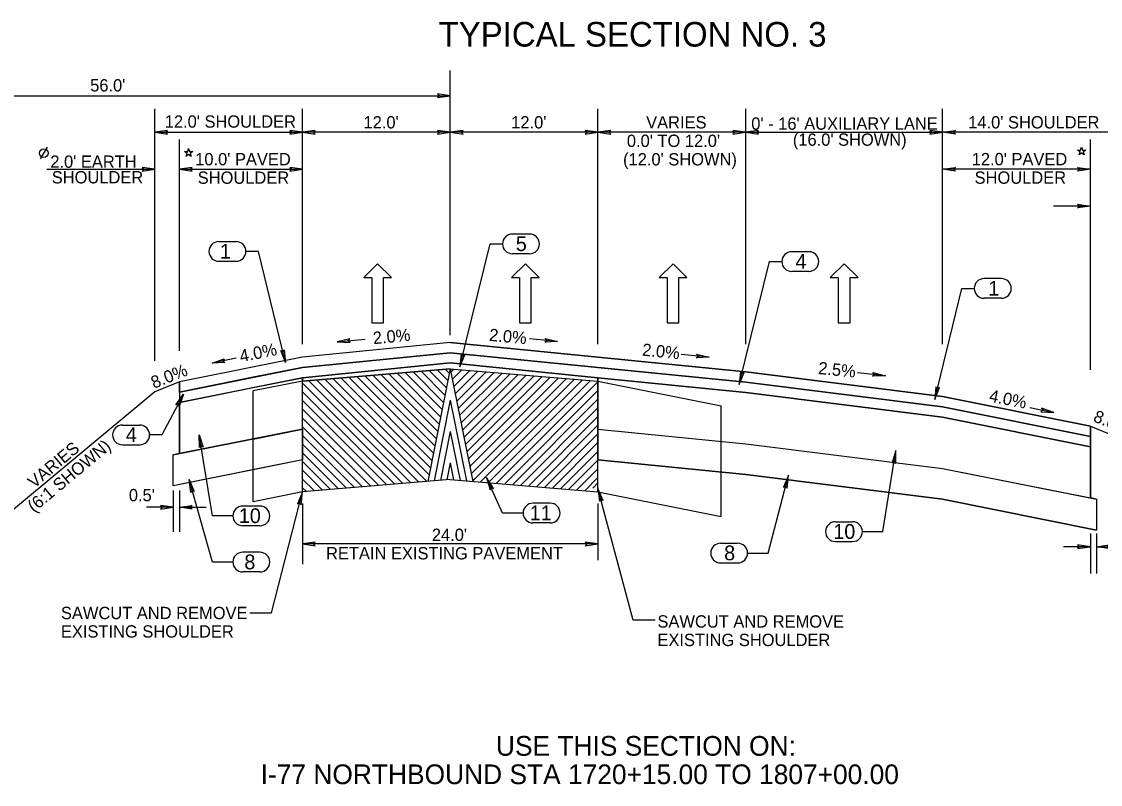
# Model space of a CAD drawing. Extents: x 2003207 to 2014043, y 843846 to 860154.
# Drawn here: x 2013648 to 2013735.7, y 844713 to 844774.9 of the extents above; entities that cross this region are included whole.
import ezdxf

# ---------------------------------------------------------------- set-up
doc = ezdxf.new("R2010")
doc.units = 0
for name, color, linetype in [('RD_EX_Road', 7, 'Continuous'), ('RD_EX_Road_txCode', 7, 'Continuous'), ('RD_QTY_Base_Course', 7, 'Continuous'), ('RD_QTY_ConcPave', 7, 'Continuous'), ('RD_QTY_Intermediate', 7, 'Continuous'), ('RD_QTY_PermVeg', 7, 'Continuous'), ('RD_QTY_Surf_Course', 7, 'Continuous'), ('RD_TX_Misc2', 7, 'Continuous'), ('RD_TX_TypSect', 7, 'Continuous')]:
    doc.layers.add(name, color=color, linetype=linetype)

msp = doc.modelspace()

# ---------------------------------------------------------------- linework, layer by layer
at = {"layer": 'RD_EX_Road'}
for p, q in [((2013682.86, 844747.226), (2013679.704, 844746.91)), ((2013682.86, 844746.75), (2013670.86, 844745.75)), ((2013676.576, 844746.226), (2013681.725, 844741.078)), ((2013677.229, 844746.281), (2013681.843, 844741.667)), ((2013677.882, 844746.335), (2013681.961, 844742.256)), ((2013678.534, 844746.39), (2013682.079, 844742.845)), ((2013679.187, 844746.444), (2013682.197, 844743.435)), ((2013679.84, 844746.498), (2013682.315, 844744.024)), ((2013680.493, 844746.553), (2013682.432, 844744.613)), ((2013682.86, 844746.75), (2013681.03, 844737.602)), ((2013681.145, 844746.607), (2013682.55, 844745.202)), ((2013681.798, 844746.662), (2013682.668, 844745.792)), ((2013682.451, 844746.716), (2013682.786, 844746.381)), ((2013682.86, 844746.75), (2013684.689, 844737.602)), ((2013682.86, 844746.75), (2013694.86, 844745.75)), ((2013682.913, 844746.483), (2013683.156, 844746.725)), ((2013683.031, 844745.894), (2013683.809, 844746.671)), ((2013683.149, 844745.304), (2013684.461, 844746.617)), ((2013683.267, 844744.715), (2013685.114, 844746.562)), ((2013683.385, 844744.126), (2013685.767, 844746.508)), ((2013683.503, 844743.537), (2013686.419, 844746.453)), ((2013683.62, 844742.947), (2013687.072, 844746.399)), ((2013683.738, 844742.358), (2013687.725, 844746.345)), ((2013683.856, 844741.769), (2013688.378, 844746.29)), ((2013683.974, 844741.179), (2013689.03, 844746.236)), ((2013670.86, 844745.75), (2013666.86, 844744.95)), ((2013670.86, 844736.754), (2013670.86, 844745.75)), ((2013670.86, 844745.579), (2013679.006, 844737.433)), ((2013671.355, 844745.791), (2013679.658, 844737.487)), ((2013672.007, 844745.846), (2013680.311, 844737.542)), ((2013672.66, 844745.9), (2013680.964, 844737.596)), ((2013673.313, 844745.955), (2013681.136, 844738.131)), ((2013673.965, 844746.009), (2013681.254, 844738.721)), ((2013674.618, 844746.063), (2013681.372, 844739.31)), ((2013675.271, 844746.118), (2013681.49, 844739.899)), ((2013675.924, 844746.172), (2013681.607, 844740.488)), ((2013684.092, 844740.59), (2013689.683, 844746.182)), ((2013684.21, 844740.001), (2013690.336, 844746.127)), ((2013684.327, 844739.412), (2013690.988, 844746.073)), ((2013684.445, 844738.822), (2013691.641, 844746.018)), ((2013684.563, 844738.233), (2013692.294, 844745.964)), ((2013684.681, 844737.644), (2013692.947, 844745.91)), ((2013685.295, 844737.551), (2013693.599, 844745.855)), ((2013685.935, 844737.483), (2013694.252, 844745.801)), ((2013686.601, 844737.442), (2013694.905, 844745.746)), ((2013694.86, 844745.75), (2013704.86, 844743.75)), ((2013694.86, 844736.754), (2013694.86, 844745.75)), ((2013666.86, 844735.954), (2013666.86, 844744.95)), ((2013670.86, 844744.872), (2013678.353, 844737.379)), ((2013687.254, 844737.388), (2013694.86, 844744.994)), ((2013670.86, 844744.165), (2013677.7, 844737.324)), ((2013682.86, 844744.201), (2013681.549, 844737.645)), ((2013682.86, 844744.201), (2013684.171, 844737.645)), ((2013687.906, 844737.334), (2013694.86, 844744.287)), ((2013704.86, 844734.754), (2013704.86, 844743.75)), ((2013670.86, 844743.458), (2013677.048, 844737.27)), ((2013670.86, 844742.751), (2013676.395, 844737.215)), ((2013688.559, 844737.279), (2013694.86, 844743.58)), ((2013689.212, 844737.225), (2013694.86, 844742.873)), ((2013670.86, 844742.044), (2013675.742, 844737.161)), ((2013689.864, 844737.171), (2013694.86, 844742.166)), ((2013670.86, 844741.336), (2013675.089, 844737.107)), ((2013682.86, 844741.651), (2013682.067, 844737.688)), ((2013682.86, 844741.651), (2013683.652, 844737.688)), ((2013690.517, 844737.116), (2013694.86, 844741.459)), ((2013670.86, 844740.629), (2013674.437, 844737.052)), ((2013691.17, 844737.062), (2013694.86, 844740.752)), ((2013670.86, 844739.922), (2013673.784, 844736.998)), ((2013670.86, 844739.215), (2013673.131, 844736.944)), ((2013691.823, 844737.007), (2013694.86, 844740.045)), ((2013692.475, 844736.953), (2013694.86, 844739.337)), ((2013670.86, 844738.508), (2013672.479, 844736.889)), ((2013682.86, 844739.102), (2013682.586, 844737.731)), ((2013682.86, 844739.102), (2013683.134, 844737.731)), ((2013693.128, 844736.899), (2013694.86, 844738.63)), ((2013670.86, 844737.801), (2013671.826, 844736.835)), ((2013682.86, 844737.754), (2013670.86, 844736.754)), ((2013682.86, 844737.754), (2013694.86, 844736.754)), ((2013693.781, 844736.844), (2013694.86, 844737.923)), ((2013694.433, 844737.065), (2013694.86, 844737.491)), ((2013670.86, 844736.754), (2013666.86, 844735.954)), ((2013670.86, 844737.094), (2013671.173, 844736.78)), ((2013694.86, 844736.754), (2013704.86, 844734.754))]:
    msp.add_line(p, q, dxfattribs=at)
at = {"layer": 'RD_QTY_Base_Course'}
for p, q in [((2013694.86, 844741.859), (2013694.86, 844739.359)), ((2013660.36, 844739.759), (2013666.86, 844741.059)), ((2013660.86, 844739.859), (2013660.36, 844739.759)), ((2013660.36, 844737.259), (2013660.36, 844739.759)), ((2013660.36, 844737.259), (2013660.36, 844739.759)), ((2013670.86, 844739.359), (2013660.86, 844737.359)), ((2013694.86, 844739.359), (2013706.86, 844738.159)), ((2013666.86, 844738.559), (2013660.36, 844737.259)), ((2013706.86, 844738.159), (2013722.86, 844736.159)), ((2013660.36, 844737.259), (2013660.36, 844737.259)), ((2013722.86, 844736.159), (2013735.36, 844733.659)), ((2013735.36, 844736.159), (2013734.86, 844736.259)), ((2013735.36, 844736.159), (2013735.36, 844733.659))]:
    msp.add_line(p, q, dxfattribs=at)
msp.add_lwpolyline([(2013666.86, 844741.059), (2013666.86, 844741.041), (2013670.86, 844741.859), (2013670.86, 844739.359), (2013666.86, 844738.559)], dxfattribs=at)
msp.add_lwpolyline([(2013694.86, 844741.859), (2013706.86, 844740.659), (2013722.86, 844738.659), (2013735.36, 844736.159), (2013735.36, 844733.659), (2013722.86, 844736.159), (2013706.86, 844738.159), (2013694.86, 844739.359)], close=True, dxfattribs=at)
at = {"layer": 'RD_QTY_ConcPave'}
for p, q in [((2013694.86, 844747.692), (2013706.86, 844746.492)), ((2013660.86, 844745.692), (2013660.86, 844744.025)), ((2013722.86, 844744.492), (2013734.86, 844742.092)), ((2013660.86, 844739.859), (2013660.86, 844744.025)), ((2013722.86, 844742.826), (2013734.86, 844740.426)), ((2013670.86, 844741.859), (2013660.86, 844739.859)), ((2013694.86, 844741.859), (2013706.86, 844740.659)), ((2013734.86, 844742.092), (2013734.86, 844741.259)), ((2013706.86, 844740.659), (2013722.86, 844738.659)), ((2013734.86, 844740.425), (2013734.86, 844736.259)), ((2013722.86, 844738.659), (2013734.86, 844736.259))]:
    msp.add_line(p, q, dxfattribs=at)
for points in [[(2013670.86, 844746.025), (2013660.86, 844744.025), (2013660.86, 844739.859), (2013670.86, 844741.859)], [(2013694.86, 844746.026), (2013694.86, 844741.859), (2013706.86, 844740.659), (2013722.86, 844738.659), (2013734.86, 844736.259), (2013734.86, 844740.425), (2013722.86, 844742.826), (2013706.86, 844744.826)]]:
    msp.add_lwpolyline(points, close=True, dxfattribs=at)
at = {"layer": 'RD_QTY_Intermediate'}
for p, q in [((2013682.86, 844748.059), (2013670.86, 844746.859)), ((2013682.86, 844748.059), (2013694.86, 844746.859)), ((2013682.86, 844747.226), (2013670.86, 844746.026)), ((2013682.86, 844747.226), (2013694.86, 844746.026)), ((2013694.86, 844746.026), (2013682.86, 844747.226)), ((2013670.86, 844746.859), (2013660.86, 844744.859)), ((2013682.86, 844746.75), (2013670.86, 844745.75)), ((2013670.86, 844745.75), (2013682.86, 844746.75)), ((2013682.86, 844746.75), (2013694.86, 844745.75)), ((2013682.86, 844746.75), (2013694.86, 844745.75)), ((2013694.86, 844746.859), (2013706.86, 844745.659)), ((2013670.86, 844746.025), (2013660.86, 844744.025)), ((2013670.86, 844745.75), (2013670.86, 844746.025)), ((2013670.86, 844746.025), (2013670.86, 844746.025)), ((2013670.86, 844746.025), (2013670.86, 844745.75)), ((2013670.86, 844745.75), (2013670.86, 844745.75)), ((2013670.86, 844745.75), (2013670.86, 844745.75)), ((2013694.86, 844746.026), (2013706.86, 844744.826)), ((2013694.86, 844746.026), (2013694.86, 844745.75)), ((2013694.86, 844745.75), (2013694.86, 844746.026)), ((2013706.86, 844745.659), (2013722.86, 844743.659)), ((2013660.86, 844744.859), (2013660.86, 844744.025)), ((2013706.86, 844744.826), (2013722.86, 844742.826)), ((2013722.86, 844743.659), (2013734.86, 844741.259)), ((2013722.86, 844742.825), (2013734.86, 844740.425)), ((2013734.86, 844741.259), (2013734.86, 844740.425))]:
    msp.add_line(p, q, dxfattribs=at)
msp.add_lwpolyline([(2013670.86, 844746.025), (2013682.86, 844747.226), (2013706.86, 844744.826), (2013722.86, 844742.826), (2013734.86, 844740.425), (2013734.86, 844741.259), (2013722.86, 844743.659), (2013706.86, 844745.659), (2013682.86, 844748.059), (2013670.86, 844746.859), (2013666.86, 844746.059), (2013660.86, 844744.859), (2013660.86, 844744.025), (2013666.86, 844745.225)], close=True, dxfattribs=at)
msp.add_lwpolyline([(2013682.86, 844747.226), (2013679.704, 844746.91), (2013670.86, 844746.025)], dxfattribs=at)
at = {"layer": 'RD_QTY_PermVeg'}
for p, q in [((2013660.86, 844745.692), (2013658.86, 844744.892)), ((2013658.86, 844744.892), (2013626.86, 844718.225)), ((2013734.86, 844742.092), (2013736.86, 844741.292))]:
    msp.add_line(p, q, dxfattribs=at)
at = {"layer": 'RD_QTY_Surf_Course'}
for p, q in [((2013682.86, 844748.892), (2013670.86, 844747.692)), ((2013682.86, 844748.892), (2013694.86, 844747.692)), ((2013670.86, 844747.692), (2013660.86, 844745.692)), ((2013706.86, 844746.492), (2013722.86, 844744.492)), ((2013660.86, 844744.859), (2013660.86, 844745.692)), ((2013660.86, 844741.525), (2013660.86, 844740.863))]:
    msp.add_line(p, q, dxfattribs=at)
msp.add_lwpolyline([(2013694.86, 844746.859), (2013706.86, 844745.659), (2013722.86, 844743.659), (2013734.86, 844741.259), (2013734.86, 844742.092), (2013722.86, 844744.492), (2013706.86, 844746.492), (2013694.86, 844747.692), (2013682.86, 844748.892), (2013670.86, 844747.692), (2013660.86, 844745.692), (2013660.86, 844744.859), (2013670.86, 844746.859), (2013682.86, 844748.059)], close=True, dxfattribs=at)
at = {"layer": 'RD_TX_Misc2'}
for p, q in [((2013689.304, 844757.692), (2013687.904, 844757.692)), ((2013664.06, 844757.077), (2013665.46, 844757.077)), ((2013689.304, 844756.092), (2013687.904, 844756.092)), ((2013711.998, 844756.255), (2013710.598, 844756.255)), ((2013664.06, 844755.477), (2013665.46, 844755.477)), ((2013711.998, 844754.655), (2013710.598, 844754.655)), ((2013727.633, 844754.071), (2013726.233, 844754.071)), ((2013727.633, 844752.471), (2013726.233, 844752.471)), ((2013656.233, 844742.182), (2013657.633, 844742.182)), ((2013656.233, 844740.582), (2013657.633, 844740.582)), ((2013690.98, 844735.835), (2013689.58, 844735.835)), ((2013667.4, 844735.606), (2013666, 844735.606)), ((2013667.4, 844734.006), (2013666, 844734.006)), ((2013690.98, 844734.235), (2013689.58, 844734.235)), ((2013714.144, 844734.326), (2013715.544, 844734.326)), ((2013704.821, 844732.585), (2013706.221, 844732.585)), ((2013714.144, 844732.726), (2013715.544, 844732.726)), ((2013667.4, 844731.852), (2013666, 844731.852)), ((2013704.821, 844730.985), (2013706.221, 844730.985)), ((2013667.4, 844730.252), (2013666, 844730.252))]:
    msp.add_line(p, q, dxfattribs=at)
for centre, start, end in [((2013687.904, 844756.892), 90, 270), ((2013689.304, 844756.892), 270, 90), ((2013664.06, 844756.277), 90, 270), ((2013665.46, 844756.277), 270, 90), ((2013710.598, 844755.455), 90, 270), ((2013711.998, 844755.455), 270, 90), ((2013726.233, 844753.271), 90, 270), ((2013727.633, 844753.271), 270, 90), ((2013656.233, 844741.382), 90, 270), ((2013657.633, 844741.382), 270, 90), ((2013689.58, 844735.035), 90, 270), ((2013690.98, 844735.035), 270, 90), ((2013666, 844734.806), 90, 270), ((2013667.4, 844734.806), 270, 90), ((2013714.144, 844733.526), 90, 270), ((2013715.544, 844733.526), 270, 90), ((2013704.821, 844731.785), 90, 270), ((2013706.221, 844731.785), 270, 90), ((2013666, 844731.052), 90, 270), ((2013667.4, 844731.052), 270, 90)]:
    msp.add_arc(centre, 0.8, start, end, dxfattribs=at)
at = {"layer": 'RD_TX_TypSect'}
for p, q in [((2013682.86, 844749.482), (2013682.86, 844770.976)), ((2013626.86, 844768.924), (2013682.86, 844768.924)), ((2013658.86, 844747.384), (2013658.86, 844767.863)), ((2013670.86, 844748.751), (2013670.86, 844767.863)), ((2013694.86, 844748.751), (2013694.86, 844767.863)), ((2013706.86, 844748.751), (2013706.86, 844767.863)), ((2013722.86, 844748.751), (2013722.86, 844767.863)), ((2013658.86, 844765.956), (2013670.86, 844765.956)), ((2013682.86, 844765.956), (2013670.86, 844765.956)), ((2013670.86, 844765.956), (2013670.86, 844765.956)), ((2013694.86, 844765.956), (2013682.86, 844765.956)), ((2013706.86, 844765.956), (2013694.86, 844765.956)), ((2013706.86, 844765.956), (2013722.86, 844765.956)), ((2013736.86, 844765.956), (2013722.86, 844765.956)), ((2013649.566, 844763.794), (2013650.132, 844764.737)), ((2013660.86, 844748.211), (2013660.86, 844765.363)), ((2013734.86, 844746.659), (2013734.86, 844765.363)), ((2013650.073, 844762.956), (2013658.86, 844762.956)), ((2013660.86, 844762.956), (2013670.86, 844762.956)), ((2013734.86, 844762.956), (2013722.86, 844762.956)), ((2013734.86, 844759.956), (2013731.866, 844759.956)), ((2013673.669, 844748.938), (2013675.948, 844749.146)), ((2013691.584, 844748.965), (2013689.305, 844749.173)), ((2013665.461, 844747.607), (2013663.51, 844747.217)), ((2013703.894, 844747.685), (2013701.618, 844747.912)), ((2013718.212, 844746.191), (2013715.936, 844746.419)), ((2013729.94, 844743.599), (2013731.891, 844743.208)), ((2013660.36, 844736.88), (2013660.36, 844733.507)), ((2013660.86, 844736.88), (2013660.86, 844733.507)), ((2013670.86, 844735.813), (2013670.86, 844730.894)), ((2013694.86, 844735.813), (2013694.86, 844731.208)), ((2013660.36, 844735.508), (2013658.192, 844735.508)), ((2013660.86, 844735.508), (2013663.027, 844735.508)), ((2013734.86, 844733.367), (2013734.86, 844730.134)), ((2013735.36, 844733.367), (2013735.36, 844730.134)), ((2013694.86, 844732.526), (2013670.86, 844732.526)), ((2013734.86, 844732.3), (2013732.692, 844732.3)), ((2013735.36, 844732.3), (2013737.527, 844732.3))]:
    msp.add_line(p, q, dxfattribs=at)
for points in [[(2013682.86, 844768.924), (2013681.821, 844769.074), (2013681.981, 844768.924), (2013681.821, 844768.775)], [(2013658.86, 844765.956), (2013659.898, 844765.806), (2013659.739, 844765.956), (2013659.898, 844766.106)], [(2013670.86, 844765.956), (2013669.821, 844766.106), (2013669.981, 844765.956), (2013669.821, 844765.806)], [(2013670.86, 844765.956), (2013671.898, 844765.806), (2013671.739, 844765.956), (2013671.898, 844766.106)], [(2013682.86, 844765.956), (2013681.821, 844766.106), (2013681.981, 844765.956), (2013681.821, 844765.806)], [(2013682.86, 844765.956), (2013683.898, 844765.806), (2013683.739, 844765.956), (2013683.898, 844766.106)], [(2013694.86, 844765.956), (2013693.821, 844766.106), (2013693.981, 844765.956), (2013693.821, 844765.806)], [(2013694.86, 844765.956), (2013695.898, 844765.806), (2013695.739, 844765.956), (2013695.898, 844766.106)], [(2013706.86, 844765.956), (2013705.821, 844766.106), (2013705.981, 844765.956), (2013705.821, 844765.806)], [(2013706.86, 844765.956), (2013707.898, 844765.806), (2013707.739, 844765.956), (2013707.898, 844766.106)], [(2013722.86, 844765.956), (2013721.821, 844766.106), (2013721.981, 844765.956), (2013721.821, 844765.806)], [(2013722.86, 844765.956), (2013723.898, 844766.106), (2013723.739, 844765.956), (2013723.898, 844765.806)], [(2013733.818, 844764.511), (2013734.072, 844764.511), (2013734.151, 844764.753), (2013734.229, 844764.511), (2013734.484, 844764.511), (2013734.278, 844764.361), (2013734.356, 844764.119), (2013734.151, 844764.269), (2013733.945, 844764.119), (2013734.024, 844764.361)], [(2013661.275, 844764.383), (2013661.529, 844764.383), (2013661.608, 844764.625), (2013661.686, 844764.383), (2013661.941, 844764.383), (2013661.735, 844764.234), (2013661.814, 844763.992), (2013661.608, 844764.141), (2013661.402, 844763.992), (2013661.481, 844764.234)], [(2013658.86, 844762.956), (2013657.821, 844763.106), (2013657.981, 844762.956), (2013657.821, 844762.806)], [(2013660.86, 844762.956), (2013661.898, 844762.806), (2013661.739, 844762.956), (2013661.898, 844763.106)], [(2013670.86, 844762.956), (2013669.821, 844763.106), (2013669.981, 844762.956), (2013669.821, 844762.806)], [(2013722.86, 844762.956), (2013723.898, 844763.106), (2013723.739, 844762.956), (2013723.898, 844762.806)], [(2013734.86, 844762.956), (2013733.821, 844762.806), (2013733.981, 844762.956), (2013733.821, 844763.106)], [(2013734.86, 844759.956), (2013733.821, 844759.806), (2013733.981, 844759.956), (2013733.821, 844760.106)], [(2013676.482, 844750.484), (2013677.442, 844750.484), (2013677.442, 844754.153), (2013678.093, 844754.153), (2013676.962, 844755.284), (2013675.83, 844754.153), (2013676.482, 844754.153)], [(2013688.482, 844750.484), (2013689.442, 844750.484), (2013689.442, 844754.153), (2013690.093, 844754.153), (2013688.962, 844755.284), (2013687.83, 844754.153), (2013688.482, 844754.153)], [(2013700.482, 844750.484), (2013701.442, 844750.484), (2013701.442, 844754.153), (2013702.093, 844754.153), (2013700.962, 844755.284), (2013699.83, 844754.153), (2013700.482, 844754.153)], [(2013714.38, 844750.484), (2013715.34, 844750.484), (2013715.34, 844754.153), (2013715.991, 844754.153), (2013714.86, 844755.284), (2013713.728, 844754.153), (2013714.38, 844754.153)], [(2013673.669, 844748.938), (2013674.717, 844748.883), (2013674.544, 844749.018), (2013674.69, 844749.182)], [(2013691.584, 844748.965), (2013690.535, 844748.911), (2013690.708, 844749.045), (2013690.563, 844749.209)], [(2013669.477, 844747.257), (2013669.084, 844748.231), (2013669.268, 844748.111), (2013669.375, 844748.302)], [(2013663.51, 844747.217), (2013664.499, 844747.567), (2013664.372, 844747.389), (2013664.558, 844747.273)], [(2013683.65, 844746.902), (2013684.043, 844747.875), (2013683.859, 844747.755), (2013683.751, 844747.946)], [(2013703.894, 844747.685), (2013702.846, 844747.639), (2013703.02, 844747.772), (2013702.876, 844747.937)], [(2013706.344, 844745.464), (2013706.736, 844746.437), (2013706.553, 844746.318), (2013706.445, 844746.509)], [(2013718.212, 844746.191), (2013717.164, 844746.145), (2013717.338, 844746.279), (2013717.194, 844746.444)], [(2013661.181, 844744.681), (2013660.829, 844743.692), (2013660.771, 844743.903), (2013660.564, 844743.832)], [(2013722.216, 844744.252), (2013722.609, 844745.225), (2013722.425, 844745.105), (2013722.317, 844745.296)], [(2013731.891, 844743.208), (2013730.902, 844743.559), (2013731.03, 844743.381), (2013730.843, 844743.265)], [(2013662.473, 844741.399), (2013662.787, 844740.397), (2013662.613, 844740.531), (2013662.49, 844740.35)], [(2013719.071, 844740.12), (2013718.758, 844739.118), (2013718.931, 844739.252), (2013719.054, 844739.07)], [(2013661.651, 844737.751), (2013662.069, 844736.788), (2013661.882, 844736.903), (2013661.779, 844736.709)], [(2013685.817, 844737.927), (2013686.102, 844736.918), (2013686.174, 844737.125), (2013686.376, 844737.04)], [(2013710.349, 844738.101), (2013709.939, 844737.135), (2013710.125, 844737.251), (2013710.229, 844737.059)], [(2013670.86, 844736.754), (2013670.459, 844735.784), (2013670.644, 844735.902), (2013670.75, 844735.711)], [(2013694.86, 844737.03), (2013694.984, 844735.988), (2013695.087, 844736.181), (2013695.274, 844736.065)], [(2013660.36, 844735.508), (2013659.321, 844735.658), (2013659.481, 844735.508), (2013659.321, 844735.358)], [(2013660.86, 844735.508), (2013661.898, 844735.658), (2013661.739, 844735.508), (2013661.898, 844735.358)], [(2013670.86, 844732.526), (2013671.898, 844732.376), (2013671.739, 844732.526), (2013671.898, 844732.676)], [(2013694.86, 844732.526), (2013693.821, 844732.676), (2013693.981, 844732.526), (2013693.821, 844732.376)], [(2013734.86, 844732.3), (2013733.821, 844732.45), (2013733.981, 844732.3), (2013733.821, 844732.15)], [(2013735.36, 844732.3), (2013736.398, 844732.45), (2013736.239, 844732.3), (2013736.398, 844732.15)]]:
    msp.add_lwpolyline(points, close=True, dxfattribs=at)
for points in [[(2013683.65, 844746.902), (2013686.095, 844756.892), (2013687.104, 844756.892)], [(2013669.477, 844747.257), (2013667.269, 844756.277), (2013666.26, 844756.277)], [(2013706.344, 844745.464), (2013708.789, 844755.455), (2013709.798, 844755.455)], [(2013722.216, 844744.252), (2013724.424, 844753.271), (2013725.433, 844753.271)], [(2013661.181, 844744.681), (2013659.442, 844741.382), (2013658.433, 844741.382)], [(2013665.2, 844734.806), (2013663.535, 844734.806), (2013662.473, 844741.399)], [(2013716.344, 844733.526), (2013718.009, 844733.526), (2013719.071, 844740.12)], [(2013665.2, 844731.052), (2013663.535, 844731.052), (2013661.651, 844737.751)], [(2013688.78, 844735.035), (2013687.114, 844735.035), (2013685.817, 844737.927)], [(2013707.021, 844731.785), (2013708.687, 844731.785), (2013710.349, 844738.101)], [(2013666.574, 844726.945), (2013668.349, 844726.945), (2013670.86, 844736.754)], [(2013699.505, 844726.327), (2013697.73, 844726.327), (2013694.86, 844737.03)]]:
    msp.add_lwpolyline(points, dxfattribs=at)
msp.add_circle((2013649.849, 844764.266), 0.35, dxfattribs=at)

# ---------------------------------------------------------------- texts
at = {"layer": 'RD_EX_Road_txCode'}
for s, p in [('USE THIS SECTION ON:', (2013686.571, 844715.331)), ('I-77 NORTHBOUND STA 1720+15.00 TO 1807+00.00', (2013667.459, 844713.025))]:
    msp.add_text(s, height=1.6, dxfattribs=at).set_placement(p)
at = {"layer": 'RD_TX_Misc2'}
for s, p in [('1', (2013664.148, 844755.692)), ('5', (2013688.186, 844756.308)), ('4', (2013710.903, 844754.87)), ('1', (2013726.571, 844752.686)), ('4', (2013656.501, 844740.797)), ('10', (2013665.683, 844734.221)), ('11', (2013689.319, 844734.45)), ('10', (2013713.981, 844732.942)), ('8', (2013705.112, 844731.201)), ('8', (2013666.136, 844730.467))]:
    msp.add_text(s, height=1.2, dxfattribs=at).set_placement(p)
at = {"layer": 'RD_TX_TypSect'}
for s, height, p in [('TYPICAL SECTION NO. 3', 2, (2013681.92, 844772.912)), ("56.0'", 1, (2013653.607, 844769.268)), ("12.0' SHOULDER", 1, (2013659.666, 844766.328)), ("12.0'", 1, (2013675.814, 844766.264)), ("12.0'", 1, (2013687.814, 844766.264)), ('VARIES', 1, (2013698.774, 844766.262)), ("14.0' SHOULDER", 1, (2013724.94, 844766.266)), ("0' - 16' AUXILIARY LANE", 1, (2013707.314, 844766.16)), ("0.0' TO 12.0'", 1, (2013697.207, 844764.762)), ("(16.0' SHOWN)", 1, (2013710.692, 844764.86)), ("2.0' EARTH", 1, (2013650.369, 844763.069)), ("10.0' PAVED", 1, (2013662.14, 844763.271)), ("(12.0' SHOWN)", 1, (2013696.9, 844763.262)), ("12.0' PAVED", 1, (2013725.222, 844763.274)), ('SHOULDER', 1, (2013650.487, 844761.802)), ('SHOULDER', 1, (2013662.344, 844761.771)), ('SHOULDER', 1, (2013725.458, 844761.774)), ("0.5'", 1, (2013656.749, 844735.993)), ("24.0'", 1, (2013681.366, 844732.772)), ('RETAIN EXISTING PAVEMENT', 1, (2013672.768, 844731.272)), ('SAWCUT AND REMOVE', 1, (2013651.232, 844726.422)), ('SAWCUT AND REMOVE', 1, (2013699.693, 844725.735)), ('EXISTING SHOULDER', 1, (2013651.232, 844724.922)), ('EXISTING SHOULDER', 1, (2013699.693, 844724.235))]:
    msp.add_text(s, height=height, dxfattribs=at).set_placement(p)
for s, rotation, p in [('2.0%', 5.2184, (2013676.62, 844748.745)), ('2.0%', 354.7816, (2013685.986, 844749.021)), ('4.0%', 11.30993, (2013665.854, 844747.274)), ('2.0%', 354.28941, (2013698.417, 844747.822)), ('2.5%', 354.28941, (2013712.719, 844746.331)), ('8.0%', 21.80141, (2013658.789, 844745.122)), ('4.0%', 348.69007, (2013726.582, 844744.104)), ('8.0%', 338.19859, (2013735.026, 844742.503)), ('VARIES', 39.80557, (2013649.058, 844736.999)), ('(6:1 SHOWN)', 39.80557, (2013649.044, 844735.036))]:
    msp.add_text(s, height=1, rotation=rotation, dxfattribs=at).set_placement(p)

doc.saveas('drawing.dxf')
